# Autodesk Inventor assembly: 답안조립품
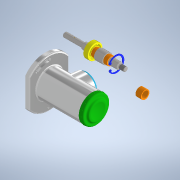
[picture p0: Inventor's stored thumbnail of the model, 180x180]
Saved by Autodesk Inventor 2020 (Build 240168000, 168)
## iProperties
Created: 2022-05
Part Number: 답안조립품
Document SubType Name: Assembly
Designer: Student
Author: Student
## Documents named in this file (11)
- C:\Users\Student\Desktop\720506V1026\답안조립품.iam
- C:\Users\Student\Desktop\720506V1026\본체.ipt
- C:\Users\Student\Desktop\720506V1026\사이드 커버.ipt
- 사이드 커버.ipt
- C:\Users\Student\Desktop\720506V1026\탑 커버.ipt
- C:\Users\Student\Desktop\720506V1026\축.ipt
- C:\Users\Student\Desktop\720506V1026\부시1.ipt
- C:\Users\Student\Desktop\720506V1026\베어링 6202.ipt
- C:\Users\Student\Desktop\720506V1026\멈춤링 35 x 1.6.ipt
- C:\Users\Student\Desktop\720506V1026\멈춤링 15 x 1.ipt
- C:\Users\Student\Desktop\720506V1026\부시2.ipt
